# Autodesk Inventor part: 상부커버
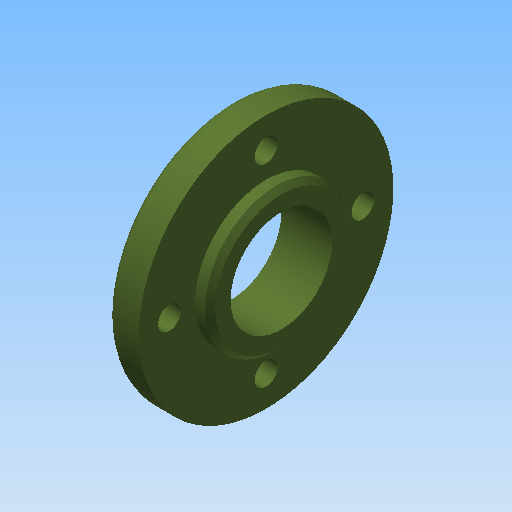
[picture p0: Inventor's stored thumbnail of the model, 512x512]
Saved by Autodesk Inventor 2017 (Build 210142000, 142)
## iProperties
Created: 2020-07
Part Number: 상부커버
Material: 알루미늄 6061
Document SubType Name: Modeling
Designer: mduedu
Density: 2.71 g/cm^3
Appearance: 올리브 녹색
Mass: 29.9794 g
Surface Area: 54.9091 cm^2
Volume: 11.0625 cm^3
Author: mduedu
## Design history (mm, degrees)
sketch "스케치1"
  geometry: L1 (0, 0)-(7, 0); L2 (7, 0)-(7, 25); L3 (7, 25)-(0, 25); L4 (0, 25)-(0, 0); L5 (7, 0)-(10, 0); L6 (10, 0)-(10, 14); L7 (10, 14)-(7, 14); L8 (7, 14)-(7, 0)
  constraints: 16 end point, 4 parallel, 2 horizontal, 2 perpendicular
  dimensions: "d0" = 50 diameter of L3 L1; "d2" = 28 diameter of L7 L5; "d3" = 7 distance of L2.end L3.end; "d4" = 10 distance between parallel lines of L6 L4
revolve "회전1" sketch "스케치1" stored, may be unused: angle "d5" = 90 deg
sketch "스케치2"
  geometry: C1 r 10 at (0, 0); 1 further point
  constraints: 1 centre point, 1 coincident
  dimensions: "d6" = 20 diameter of C1
extrude "돌출1" cut sketch "스케치2" stored distance "d7" = 10; taper "d8" = 0 deg
chamfer "모따기1" distance "d9" = 1; stored, may be unused: second distance "d10" = 2, angle "d11" = 45 deg
fillet "모깎기1" dims "d12" = 3
sketch "스케치3" dims "d13" = 38
  geometry: 3 further points
  constraints: 2 vertical alignment, 1 coincident, 2 other
hole "구멍1" sketch "스케치3" at (0, 19) diameter "d14" = 4.5; stored, may be unused: countersink angle "d18" = 90 deg, drill point angle "d20" = 118 deg; dims "d15" = 6, "d16" = 8, "d17" = 4.4, "d19" = 8
node "솔리드1"
pattern_circular "원형 패턴1" dims angle "d22" = 360 deg
